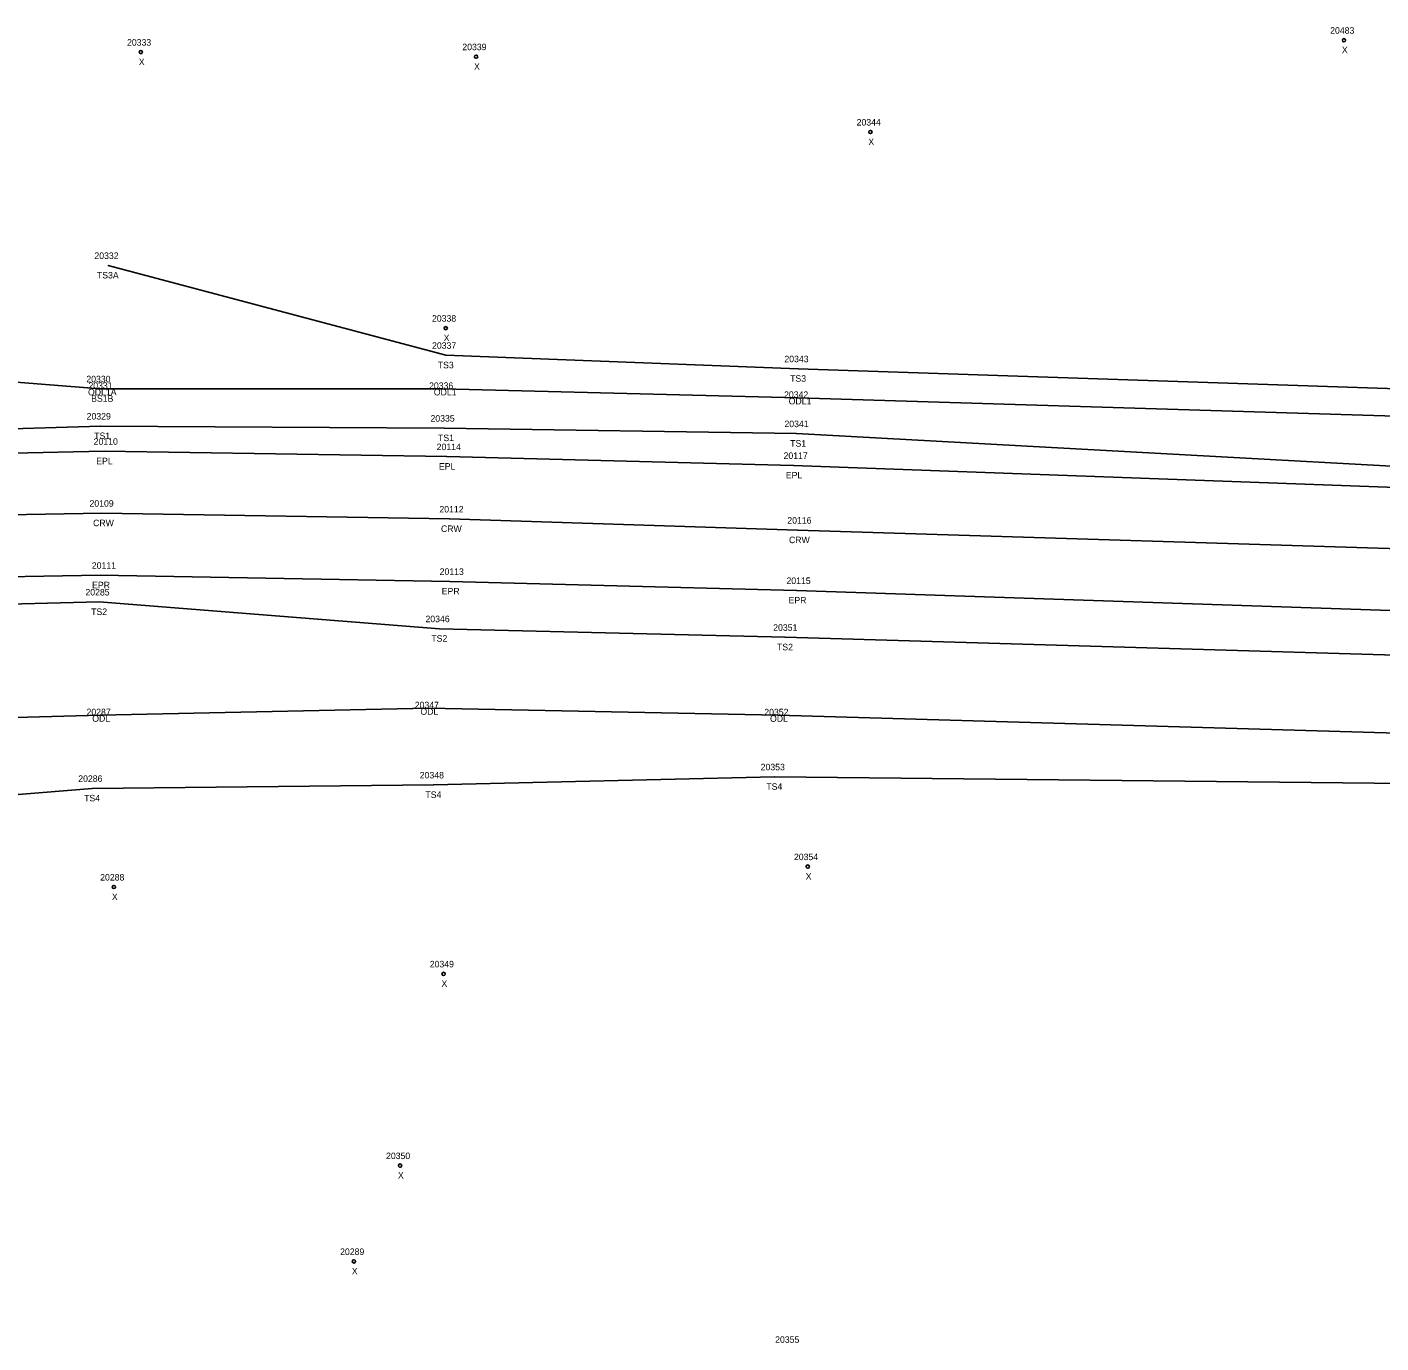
# Model space of a CAD drawing. Extents: x 1966740 to 1969291, y 1117378 to 1118461.
# Drawn here: x 1968094.2 to 1968302.4, y 1117802.2 to 1118004.7 of the extents above; entities that cross this region are included whole.
import ezdxf

# ---------------------------------------------------------------- set-up
doc = ezdxf.new("R2010")
doc.units = 0
for name, color, linetype in [('RD_DTM_BkLn1', 7, 'Continuous'), ('RD_DTM_BkLn2', 7, 'Continuous'), ('RD_EX_H2O', 7, 'Continuous'), ('RD_EX_H2O_txCode', 7, 'Continuous'), ('RD_EX_Road', 7, 'Continuous'), ('RD_EX_Road_txCode', 7, 'Continuous'), ('RD_SMD_Locator', 7, 'Continuous'), ('RD_SMD_Misc', 7, 'Continuous')]:
    doc.layers.add(name, color=color, linetype=linetype)

msp = doc.modelspace()

# ---------------------------------------------------------------- linework, layer by layer
at = {"layer": 'RD_DTM_BkLn1'}
msp.add_lwpolyline([(1967878.98, 1117895.46), (1967922.07, 1117909.4), (1967968.89, 1117921.38), (1968013.49, 1117926.44), (1968059.29, 1117929.05), (1968105.63, 1117929.86), (1968159.12, 1117928.97), (1968212.65, 1117927.25), (1968318.5, 1117923.95), (1968422.42, 1117919.39), (1968529.36, 1117916.3)], dxfattribs=at)
at = {"layer": 'RD_DTM_BkLn2'}
for points in [[(1968106.63, 1117967.98), (1968158.56, 1117954.16), (1968212.75, 1117952.09), (1968371.01, 1117946.77)], [(1967966.69, 1117955.54), (1968012.01, 1117954.01), (1968059.56, 1117952.62), (1968105.42, 1117949)], [(1967874.77, 1117908.42), (1967879.51, 1117916.91), (1967881.27, 1117924.39), (1967885.24, 1117929.22), (1967913.7, 1117935.63), (1967966.11, 1117937.12), (1968012.39, 1117940.75), (1968059.42, 1117941.87), (1968105.44, 1117943.27), (1968158.32, 1117942.95), (1968212.48, 1117942.1), (1968371.25, 1117933.41), (1968422.85, 1117933.68), (1968531.49, 1117931.42)], [(1967884.1, 1117882.92), (1967891.06, 1117879.24), (1967898.84, 1117879.11), (1967924.17, 1117888.04), (1967954.33, 1117900.3), (1967970.81, 1117903.15), (1968012.93, 1117910.83), (1968059.62, 1117915.05), (1968105.25, 1117916.2), (1968157.57, 1117912.09), (1968210.74, 1117910.77), (1968320.32, 1117907.54), (1968423.18, 1117904.83), (1968528.99, 1117899.6)], [(1968058.02, 1117883.74), (1968104.17, 1117887.52), (1968156.67, 1117888.05), (1968209.1, 1117889.3), (1968320.79, 1117888.13), (1968422.17, 1117888.28), (1968528.68, 1117880.51)]]:
    msp.add_lwpolyline(points, dxfattribs=at)
at = {"layer": 'RD_EX_H2O'}
for points in [[(1968105.42, 1117949), (1968158.12, 1117948.98), (1968212.69, 1117947.6), (1968373.17, 1117942.71)], [(1967868.28, 1117817.14), (1967892.54, 1117814.5), (1967928.24, 1117834.22), (1967973.92, 1117854.29), (1967982.67, 1117861.15), (1968021.78, 1117883.3), (1968056.97, 1117897.44), (1968105.42, 1117898.77), (1968155.9, 1117899.84), (1968209.66, 1117898.76), (1968320.81, 1117895.57), (1968371.06, 1117895.25)]]:
    msp.add_lwpolyline(points, dxfattribs=at)
at = {"layer": 'RD_EX_Road'}
for points in [[(1967878.98, 1117895.46), (1967875.66, 1117903.48), (1967919.49, 1117917.47), (1967966.4, 1117928.95), (1968012.66, 1117935.42), (1968058.94, 1117938.37), (1968105.99, 1117939.39), (1968158.7, 1117938.56), (1968212.05, 1117937.21), (1968318.79, 1117933.28), (1968422.76, 1117929.93), (1968530.54, 1117925.7)], [(1967878.98, 1117895.46), (1967883.11, 1117885.63), (1967924.99, 1117899.59), (1967970.68, 1117910.78), (1968014.42, 1117916.56), (1968059.13, 1117919.49), (1968105.39, 1117920.31), (1968159.16, 1117919.37), (1968212.5, 1117917.97), (1968317.55, 1117914.44), (1968421.52, 1117910.75), (1968527.82, 1117906.41)]]:
    msp.add_lwpolyline(points, dxfattribs=at)
at = {"layer": 'RD_SMD_Locator'}
for centre, radius in [((1968296.69, 1118002.64), 0.25), ((1968111.65, 1118000.8), 0.25), ((1968163.22, 1118000.1), 0.25), ((1968223.86, 1117988.51), 0.25), ((1968106.63, 1117967.98), 0.001), ((1968158.55, 1117958.33), 0.25), ((1968158.56, 1117954.16), 0.001), ((1968212.75, 1117952.09), 0.001), ((1968105.42, 1117949), 0.001), ((1968105.42, 1117949), 0.001), ((1968158.12, 1117948.98), 0.001), ((1968212.69, 1117947.6), 0.001), ((1968105.44, 1117943.27), 0.001), ((1968158.32, 1117942.95), 0.001), ((1968212.48, 1117942.1), 0.001), ((1968105.99, 1117939.39), 0.001), ((1968158.7, 1117938.56), 0.001), ((1968212.05, 1117937.21), 0.001), ((1968105.63, 1117929.86), 0.001), ((1968159.12, 1117928.97), 0.001), ((1968212.65, 1117927.25), 0.001), ((1968105.39, 1117920.31), 0.001), ((1968159.16, 1117919.37), 0.001), ((1968212.5, 1117917.97), 0.001), ((1968105.25, 1117916.2), 0.001), ((1968157.57, 1117912.09), 0.001), ((1968210.74, 1117910.77), 0.001), ((1968155.9, 1117899.84), 0.001), ((1968105.42, 1117898.77), 0.001), ((1968209.66, 1117898.76), 0.001), ((1968209.1, 1117889.3), 0.001), ((1968104.17, 1117887.52), 0.001), ((1968156.67, 1117888.05), 0.001), ((1968214.22, 1117875.48), 0.25), ((1968107.51, 1117872.34), 0.25), ((1968158.21, 1117858.98), 0.25), ((1968151.52, 1117829.48), 0.25), ((1968144.42, 1117814.73), 0.25)]:
    msp.add_circle(centre, radius, dxfattribs=at)

# ---------------------------------------------------------------- texts
at = {"layer": 'RD_EX_H2O_txCode'}
for s, p in [('20331', (1968103.59, 1117949)), ('20336', (1968155.98, 1117948.98)), ('ODL1A', (1968103.53, 1117948)), ('ODL1', (1968156.71, 1117947.98)), ('20342', (1968210.58, 1117947.6)), ('ODL1', (1968211.29, 1117946.6)), ('20287', (1968103.3, 1117898.77)), ('20347', (1968153.78, 1117899.84)), ('ODL', (1968154.65, 1117898.84)), ('20352', (1968207.54, 1117898.76)), ('ODL', (1968104.18, 1117897.77)), ('ODL', (1968208.42, 1117897.76))]:
    msp.add_text(s, height=1, dxfattribs=at).set_placement(p)
at = {"layer": 'RD_EX_Road_txCode'}
for s, p in [('20110', (1968104.4, 1117940.39)), ('20114', (1968157.15, 1117939.56)), ('20117', (1968210.5, 1117938.21)), ('EPL', (1968104.79, 1117937.39)), ('EPL', (1968157.5, 1117936.56)), ('EPL', (1968210.85, 1117935.21)), ('20111', (1968104.12, 1117921.31)), ('20113', (1968157.61, 1117920.37)), ('EPR', (1968104.16, 1117918.31)), ('EPR', (1968157.93, 1117917.37)), ('20115', (1968210.95, 1117918.97)), ('EPR', (1968211.27, 1117915.97))]:
    msp.add_text(s, height=1, dxfattribs=at).set_placement(p)
at = {"layer": 'RD_SMD_Misc'}
for s, p in [('20483', (1968294.57, 1118003.64)), ('20333', (1968109.53, 1118001.8)), ('20339', (1968161.1, 1118001.1)), ('X', (1968296.37, 1118000.64)), ('X', (1968111.34, 1117998.8)), ('X', (1968162.9, 1117998.1)), ('20344', (1968221.74, 1117989.51)), ('X', (1968223.54, 1117986.51)), ('20332', (1968104.51, 1117968.98)), ('TS3A', (1968104.9, 1117965.98)), ('20338', (1968156.43, 1117959.33)), ('20337', (1968156.44, 1117955.16)), ('X', (1968158.23, 1117956.33)), ('20343', (1968210.63, 1117953.09)), ('TS3', (1968157.32, 1117952.16)), ('20330', (1968103.27, 1117950)), ('TS3', (1968211.51, 1117950.09)), ('BS1B', (1968104.01, 1117947)), ('20329', (1968103.32, 1117944.27)), ('20335', (1968156.2, 1117943.95)), ('20341', (1968210.64, 1117943.1)), ('TS1', (1968104.48, 1117941.27)), ('TS1', (1968157.36, 1117940.95)), ('TS1', (1968211.52, 1117940.1)), ('20109', (1968103.76, 1117930.86)), ('20112', (1968157.57, 1117929.97)), ('CRW', (1968104.31, 1117927.86)), ('20116', (1968211.08, 1117928.25)), ('CRW', (1968157.81, 1117926.97)), ('CRW', (1968211.34, 1117925.25)), ('20285', (1968103.13, 1117917.2)), ('TS2', (1968104.01, 1117914.2)), ('20346', (1968155.43, 1117913.09)), ('20351', (1968208.91, 1117911.77)), ('TS2', (1968156.33, 1117910.09)), ('TS2', (1968209.5, 1117908.77)), ('20353', (1968206.98, 1117890.3)), ('20286', (1968102.03, 1117888.52)), ('20348', (1968154.55, 1117889.05)), ('TS4', (1968155.42, 1117886.05)), ('TS4', (1968207.85, 1117887.3)), ('TS4', (1968102.93, 1117885.52)), ('20354', (1968212.1, 1117876.48)), ('20288', (1968105.4, 1117873.34)), ('X', (1968213.91, 1117873.48)), ('X', (1968107.2, 1117870.34)), ('20349', (1968156.09, 1117859.98)), ('X', (1968157.89, 1117856.98)), ('20350', (1968149.36, 1117830.48)), ('X', (1968151.2, 1117827.48)), ('20289', (1968142.3, 1117815.73)), ('X', (1968144.1, 1117812.73)), ('20355', (1968209.21, 1117802.21))]:
    msp.add_text(s, height=1, dxfattribs=at).set_placement(p)

doc.saveas('drawing.dxf')
